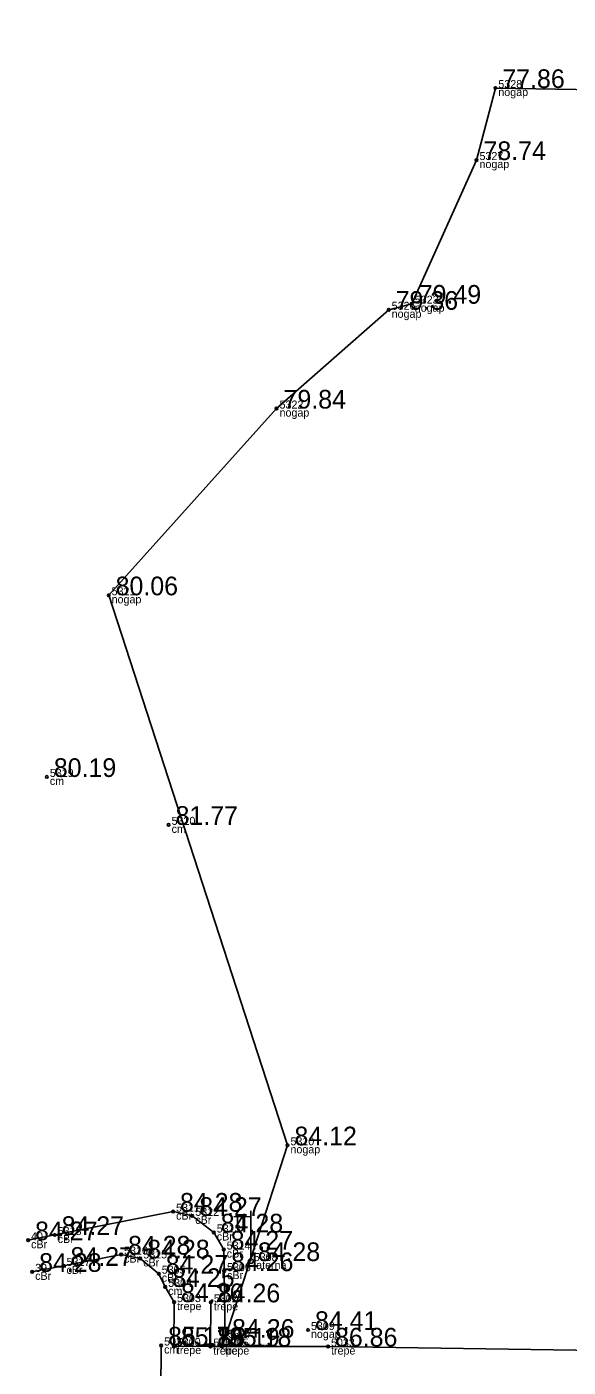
# Model space of a CAD drawing. Extents: x 614911 to 615803, y 262110 to 264311.
# Drawn here: x 615604.9 to 615625.2, y 263133.6 to 263183.8 of the extents above; entities that cross this region are included whole.
import ezdxf

# ---------------------------------------------------------------- set-up
doc = ezdxf.new("R2010")
doc.units = 0
for name, color, linetype in [('Level 31', 7, 'Continuous'), ('Level 37', 7, 'Continuous'), ('Level 44', 7, 'Continuous'), ('Level 53', 7, 'Continuous'), ('Level 54', 7, 'Continuous'), ('Level 57', 7, 'Continuous'), ('Level 58', 7, 'Continuous')]:
    doc.layers.add(name, color=color, linetype=linetype)

msp = doc.modelspace()

# ---------------------------------------------------------------- linework, layer by layer
at = {"layer": 'Level 31'}
msp.add_lwpolyline([(615645.203, 263181.984), (615630.246, 263183.814), (615628.514, 263181.419), (615622.47, 263181.52), (615621.763, 263178.82), (615619.334, 263173.437), (615618.468, 263173.209), (615614.263, 263169.507), (615607.963, 263162.509), (615614.672, 263141.896), (615612.332, 263134.683)], dxfattribs=at)
at = {"layer": 'Level 37'}
for p, q in [((615610.409, 263134.375), (615610.417, 263136.021)), ((615611.797, 263136.012), (615611.778, 263134.352)), ((615609.914, 263132.628), (615609.931, 263134.394)), ((615616.193, 263134.355), (615628.721, 263134.164))]:
    msp.add_line(p, q, dxfattribs=at)
for points in [[(615604.941, 263138.338), (615605.938, 263138.536), (615610.379, 263139.41), (615611.101, 263139.252), (615611.907, 263138.629), (615612.279, 263137.989), (615612.292, 263137.18), (615612.332, 263134.683), (615612.213, 263134.353)], [(615605.094, 263137.154), (615606.271, 263137.379), (615608.429, 263137.801), (615609.149, 263137.657), (615609.843, 263137.085), (615610.084, 263136.589), (615610.417, 263136.021)], [(615616.193, 263134.355), (615612.213, 263134.353), (615611.778, 263134.352), (615610.409, 263134.375)]]:
    msp.add_lwpolyline(points, dxfattribs=at)
at = {"layer": 'Level 44'}
for p, q in [((615613.295, 263139.225), (615612.66, 263139.22)), ((615612.795, 263139.221), (615612.795, 263138.829)), ((615613.005, 263139.223), (615613.005, 263138.829)), ((615613.295, 263137.558), (615613.295, 263139.441))]:
    msp.add_line(p, q, dxfattribs=at)
msp.add_circle((615613.295, 263137.558), 0.09, dxfattribs=at)
msp.add_ellipse((615612.9, 263138.829), major_axis=(0, 0.151), ratio=0.695971, start_param=1.570796, end_param=4.712389, dxfattribs=at)
at = {"layer": 'Level 57'}
for centre in [(615622.47, 263181.52), (615621.763, 263178.82), (615618.468, 263173.209), (615619.334, 263173.437), (615614.263, 263169.507), (615607.963, 263162.509), (615605.645, 263155.701), (615610.212, 263153.906), (615614.672, 263141.896), (615610.379, 263139.41), (615611.101, 263139.252), (615605.938, 263138.536), (615611.907, 263138.629), (615604.941, 263138.338), (615608.429, 263137.801), (615609.149, 263137.657), (615612.279, 263137.989), (615605.094, 263137.154), (615606.271, 263137.379), (615609.843, 263137.085), (615612.292, 263137.18), (615610.084, 263136.589), (615610.417, 263136.021), (615611.797, 263136.012), (615612.332, 263134.683), (615615.441, 263134.976), (615609.931, 263134.394), (615610.409, 263134.375), (615611.778, 263134.352), (615612.213, 263134.353), (615616.193, 263134.355)]:
    msp.add_circle(centre, 0.05, dxfattribs=at)
at = {"layer": 'Level 58'}
for centre in [(615622.47, 263181.52), (615621.763, 263178.82), (615618.468, 263173.209), (615619.334, 263173.437), (615614.263, 263169.507), (615607.963, 263162.509), (615605.645, 263155.701), (615610.212, 263153.906), (615614.672, 263141.896), (615610.379, 263139.41), (615611.101, 263139.252), (615605.938, 263138.536), (615611.907, 263138.629), (615604.941, 263138.338), (615608.429, 263137.801), (615609.149, 263137.657), (615612.279, 263137.989), (615605.094, 263137.154), (615606.271, 263137.379), (615609.843, 263137.085), (615612.292, 263137.18), (615610.084, 263136.589), (615610.417, 263136.021), (615611.797, 263136.012), (615612.332, 263134.683), (615615.441, 263134.976), (615609.931, 263134.394), (615610.409, 263134.375), (615611.778, 263134.352), (615612.213, 263134.353), (615616.193, 263134.355)]:
    msp.add_circle(centre, 0.05, dxfattribs=at)

# ---------------------------------------------------------------- texts
at = {"layer": 'Level 53'}
for s, p in [(' nogap', (615622.47, 263181.22)), (' nogap', (615621.763, 263178.52)), (' nogap', (615619.334, 263173.137)), (' nogap', (615618.468, 263172.909)), (' nogap', (615614.263, 263169.207)), (' nogap', (615607.963, 263162.209)), (' cm', (615605.645, 263155.401)), (' cm', (615610.212, 263153.606)), (' nogap', (615614.672, 263141.596)), (' cBr', (615610.379, 263139.11)), (' cBr', (615611.101, 263138.952)), (' cBr', (615611.907, 263138.329)), (' cBr', (615604.941, 263138.038)), (' cBr', (615605.938, 263138.236)), (' cBr', (615608.429, 263137.501)), (' cBr', (615609.149, 263137.357)), (' cBr', (615612.279, 263137.689)), (' cBr', (615605.094, 263136.854)), (' cBr', (615606.271, 263137.079)), (' cBr', (615609.843, 263136.785)), (' cBr', (615612.292, 263136.88)), (' laterna', (615613.295, 263137.258)), (' cm', (615610.084, 263136.289)), (' trepe', (615610.417, 263135.721)), (' trepe', (615611.797, 263135.712)), (' cm', (615612.332, 263134.383)), (' nogap', (615615.441, 263134.676)), (' cm', (615609.931, 263134.094)), (' trepe', (615610.409, 263134.075)), (' trepe', (615611.778, 263134.052)), (' trepe', (615612.213, 263134.053)), (' trepe', (615616.193, 263134.055))]:
    msp.add_text(s, height=0.3, dxfattribs=at).set_placement(p)
at = {"layer": 'Level 54'}
for s, p in [(' 5328', (615622.47, 263181.52)), (' 5327', (615621.763, 263178.82)), (' 5326', (615618.468, 263173.209)), (' 5323', (615619.334, 263173.437)), (' 5322', (615614.263, 263169.507)), (' 5321', (615607.963, 263162.509)), (' 5319', (615605.645, 263155.701)), (' 5320', (615610.212, 263153.906)), (' 5310', (615614.672, 263141.896)), (' 5311', (615610.379, 263139.41)), (' 5312', (615611.101, 263139.252)), (' 40', (615604.941, 263138.338)), (' 5318', (615605.938, 263138.536)), (' 5313', (615611.907, 263138.629)), (' 5316', (615608.429, 263137.801)), (' 5314', (615612.279, 263137.989)), (' 5317', (615606.271, 263137.379)), (' 5315', (615609.149, 263137.657)), (' 5308', (615613.295, 263137.558)), (' 39', (615605.094, 263137.154)), (' 5305', (615609.843, 263137.085)), (' 5306', (615612.292, 263137.18)), (' 5304', (615610.084, 263136.589)), (' 5303', (615610.417, 263136.021)), (' 5302', (615611.797, 263136.012)), (' 5309', (615615.441, 263134.976)), (' 5037', (615609.931, 263134.394)), (' 5300', (615610.409, 263134.375)), (' 5301', (615611.778, 263134.352)), (' 5035', (615612.213, 263134.353)), (' 5307', (615612.332, 263134.683)), (' 5033', (615616.193, 263134.355))]:
    msp.add_text(s, height=0.3, dxfattribs=at).set_placement(p)
at = {"layer": 'Level 58'}
for s, p in [(' 77.86', (615622.47, 263181.52)), (' 78.74', (615621.763, 263178.82)), (' 79.36', (615618.468, 263173.209)), (' 79.49', (615619.334, 263173.437)), (' 79.84', (615614.263, 263169.507)), (' 80.06', (615607.963, 263162.509)), (' 80.19', (615605.645, 263155.701)), (' 81.77', (615610.212, 263153.906)), (' 84.12', (615614.672, 263141.896)), (' 84.28', (615610.379, 263139.41)), (' 84.27', (615611.101, 263139.252)), (' 84.27', (615605.938, 263138.536)), (' 84.28', (615611.907, 263138.629)), (' 84.27', (615604.941, 263138.338)), (' 84.27', (615612.279, 263137.989)), (' 84.27', (615606.271, 263137.379)), (' 84.28', (615608.429, 263137.801)), (' 84.28', (615609.149, 263137.657)), (' 84.28', (615613.295, 263137.558)), (' 84.28', (615605.094, 263137.154)), (' 84.27', (615609.843, 263137.085)), (' 84.26', (615612.292, 263137.18)), (' 84.25', (615610.084, 263136.589)), (' 84.26', (615610.417, 263136.021)), (' 84.26', (615611.797, 263136.012)), (' 84.41', (615615.441, 263134.976)), (' 85.17', (615609.931, 263134.394)), (' 85.19', (615610.409, 263134.375)), (' 84.26', (615612.332, 263134.683)), (' 85.19', (615611.778, 263134.352)), (' 85.18', (615612.213, 263134.353)), (' 86.86', (615616.193, 263134.355))]:
    msp.add_text(s, height=0.7, dxfattribs=at).set_placement(p)

doc.saveas('drawing.dxf')
